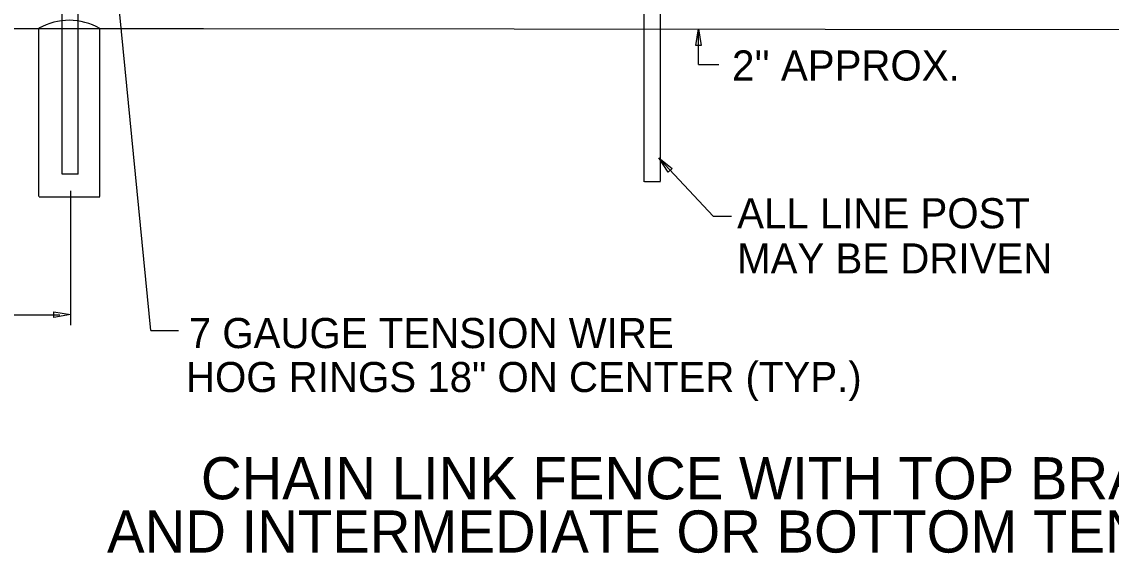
# Model space of a CAD drawing. Extents: x 0 to 2.85, y -0.1 to 1.83.
# Drawn here: x 0.694 to 1.0563, y 0.6316 to 0.8081 of the extents above; entities that cross this region are included whole.
import ezdxf

# ---------------------------------------------------------------- set-up
doc = ezdxf.new("R2010")
doc.units = 0
for name, color, linetype in [('CT_CSHT_GeneralLabel', 7, 'Continuous'), ('CT_Dimensions', 7, 'Continuous'), ('sb_Chainlink Fence', 7, 'Continuous'), ('sb_Existing Concrete', 7, 'Continuous'), ('sb_Existing Structural Steel', 7, 'Continuous')]:
    doc.layers.add(name, color=color, linetype=linetype)

msp = doc.modelspace()

# ---------------------------------------------------------------- linework, layer by layer
at = {"layer": 'CT_Dimensions'}
for p, q in [((0.73691, 0.70564), (0.72589, 0.81823)), ((0.91905, 0.79398), (0.91905, 0.80484)), ((0.91905, 0.79398), (0.92577, 0.79394)), ((0.90622, 0.76251), (0.92391, 0.74353)), ((0.90106, 0.75506), (0.90644, 0.75506)), ((0.71018, 0.75202), (0.71018, 0.70738)), ((0.92391, 0.74353), (0.93, 0.74353)), ((0.32318, 0.71078), (0.70672, 0.71078)), ((0.73691, 0.70564), (0.74618, 0.70564))]:
    msp.add_line(p, q, dxfattribs=at)
for points in [[(0.91812, 0.80031), (0.91904, 0.8058), (0.91996, 0.80031)], [(0.9089, 0.75823), (0.90589, 0.76292), (0.91026, 0.75946)], [(0.70474, 0.71178), (0.71024, 0.71086), (0.70474, 0.70995)]]:
    msp.add_lwpolyline(points, close=True, dxfattribs=at)
at = {"layer": 'sb_Chainlink Fence'}
for p, q in [((0.32835, 0.80627), (0.75445, 0.80587)), ((0.75445, 0.80587), (1.13401, 0.80557))]:
    msp.add_line(p, q, dxfattribs=at)
at = {"layer": 'sb_Existing Concrete'}
for p, q in [((0.69973, 0.75013), (0.69973, 0.80594)), ((0.71996, 0.75008), (0.71996, 0.80589)), ((0.69981, 0.75003), (0.72, 0.75003))]:
    msp.add_line(p, q, dxfattribs=at)
msp.add_arc((0.70978, 0.78834), 0.02029, 59.953, 119.6876, dxfattribs=at)
at = {"layer": 'sb_Existing Structural Steel'}
for p, q in [((0.70744, 0.80791), (0.70751, 0.91455)), ((0.71281, 0.80784), (0.71291, 0.91474)), ((0.901, 0.80573), (0.90109, 0.91511)), ((0.90642, 0.80585), (0.90651, 0.91531)), ((0.70742, 0.75758), (0.70744, 0.80791)), ((0.71282, 0.75754), (0.71281, 0.80784)), ((0.901, 0.755), (0.901, 0.80573)), ((0.90642, 0.75517), (0.90642, 0.80585)), ((0.71281, 0.75754), (0.70745, 0.75754))]:
    msp.add_line(p, q, dxfattribs=at)

# ---------------------------------------------------------------- texts
at = {"layer": 'CT_CSHT_GeneralLabel'}
for s, p in [('CHAIN LINK FENCE WITH TOP BRACE RAIL', (0.75359, 0.64953)), ('AND INTERMEDIATE OR BOTTOM TENSION WIRE', (0.72239, 0.63183))]:
    msp.add_text(s, height=0.014, dxfattribs=at).set_placement(p)
at = {"layer": 'CT_Dimensions'}
for s, p in [("2'' APPROX.", (0.9302, 0.78863)), ('ALL LINE POST', (0.9319, 0.73955)), ('MAY BE DRIVEN', (0.9319, 0.72455)), ('7 GAUGE TENSION WIRE', (0.74957, 0.69975)), ('HOG RINGS 18" ON CENTER (TYP.)', (0.74863, 0.68515))]:
    msp.add_text(s, height=0.01, dxfattribs=at).set_placement(p)

doc.saveas('drawing.dxf')
